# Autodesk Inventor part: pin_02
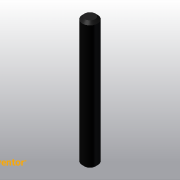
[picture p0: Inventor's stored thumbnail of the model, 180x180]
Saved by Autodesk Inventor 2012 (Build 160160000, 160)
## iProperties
Company: Autodesk
Shininess: 64.0
Length Units: 11269
Angle Units: 11279
Time Units: 11290
Mass Units: 11283
Length Display Precision: 3
Angle Display Precision: 2
Compacted: True
Part Number: pin_02
Document SubType Name: Modeling
Created: 2002-10
Designer: Lieven Grauls
Stock Number: pin_02
Project: Valve Techcamp 2008
Density: 1 g/cm^3
Mass: 0.172288 g
Surface Area: 2.41863 cm^2
Volume: 0.172288 cm^3
Material: Default
Density: 0.0
Volumn: 0.0
Area: 0.0
PropertySet Name: Model Information
Control State: 0
Master: False
Checked Out: False
Author: Lieven Grauls
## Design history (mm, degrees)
sketch "Sketch1"
  geometry: C1 r 1.49 at (0, 0); 1 further point
  constraints: 1 centre point, 1 coincident
  dimensions: "d0" = 2.98 diameter of C1
extrude "Extrusion1" new body sketch "Sketch1" distance "d1" = 25; taper "d2" = 0 deg
chamfer "Chamfer1" distance "d3" = 0.5; stored, may be unused: second distance "d4" = 2, angle "d5" = 45 deg
node "Volumenkörper1"
node "Volumenkörpern"
node "Oberflächenkörpern"
